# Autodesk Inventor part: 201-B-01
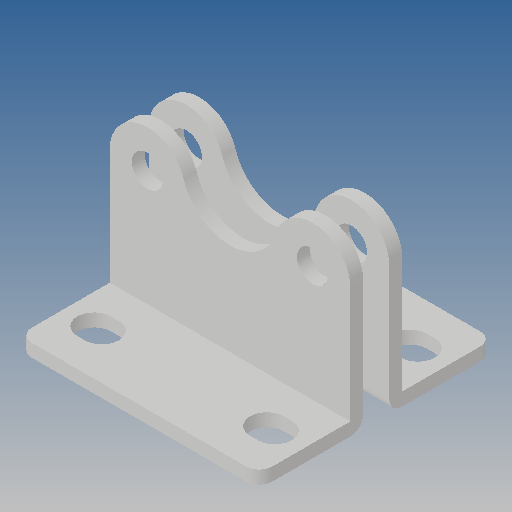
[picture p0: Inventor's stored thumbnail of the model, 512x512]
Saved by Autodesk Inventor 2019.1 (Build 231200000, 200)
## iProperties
Created: 2012-01
Part Number: 201-B-01
Material: Ogólny
Document SubType Name: Modeling
Designer: CADENGINEERING4
Density: 1 g/cm^3
Appearance: Domyślna
Author: CADENGINEERING4
Revision Number: ÈÎºÎ
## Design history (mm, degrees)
feature "Ô²½Ç1"
feature "¾µÏò3"
node "Bryła1"
node "Bryła2"
